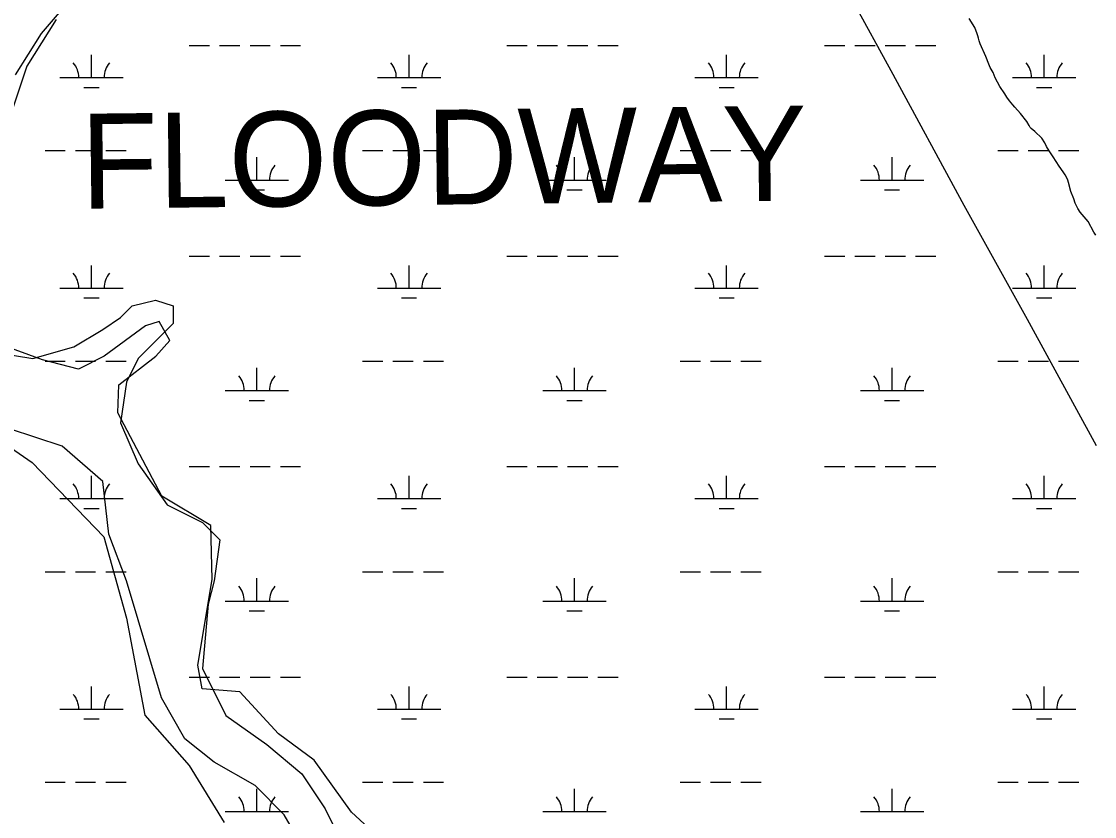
# Model space of a CAD drawing. Extents: x 3177185 to 3215018, y 812988 to 838321.
# Drawn here: x 3187840 to 3189536, y 825317 to 826573 of the extents above; entities that cross this region are included whole.
import ezdxf

# ---------------------------------------------------------------- set-up
doc = ezdxf.new("R2010")
doc.units = 0
for name, color, linetype in [('V-RIVR-IDEN', 7, 'Continuous'), ('V-SITE-VEGE', 7, 'Continuous'), ('V-TOPO-SHOR', 7, 'Continuous'), ('V-WETL-SWMP', 7, 'Continuous')]:
    doc.layers.add(name, color=color, linetype=linetype)

msp = doc.modelspace()

# ---------------------------------------------------------------- linework, layer by layer
at = {"layer": 'V-SITE-VEGE'}
for p, q in [((3187718.2, 825972.5), (3187856.6, 825876.3)), ((3187856.6, 825876.3), (3187969.7, 825759.2)), ((3187969.7, 825759.2), (3188005.9, 825630.4)), ((3188005.9, 825630.4), (3188035, 825477.1)), ((3188035, 825477.1), (3188104.7, 825397.8)), ((3188104.7, 825397.8), (3188160.3, 825307.4))]:
    msp.add_line(p, q, dxfattribs=at)
for points in [[(3189094.5, 826713.4), (3189213.8, 826495.9), (3189328.9, 826283), (3189429.2, 826103), (3189538.3, 825903.2)], [(3187830.5, 826489), (3187871.7, 826554.4), (3187906.1, 826594.7)], [(3189353.4, 826542.7), (3189352.2, 826547.1), (3189351.4, 826550.7), (3189350.2, 826554), (3189346.2, 826563.7), (3189337.7, 826577.9)], [(3189537.8, 826235.6), (3189534.5, 826240.4), (3189525.3, 826257), (3189512.8, 826272), (3189509.1, 826277.7), (3189505.1, 826286.2), (3189502.7, 826293.1), (3189498.2, 826304.4), (3189494.6, 826318.6), (3189493.4, 826322.7), (3189492.2, 826325.1), (3189489, 826331.2), (3189486.2, 826335.6), (3189479.7, 826344.9), (3189470, 826359.5), (3189464, 826368.8), (3189459.9, 826375.7), (3189457.1, 826381.4), (3189452.3, 826388.7), (3189441.4, 826399.6), (3189435.7, 826404.1), (3189434.1, 826405.7), (3189432.1, 826409), (3189428.5, 826415.4), (3189418.8, 826428), (3189409.5, 826438.1), (3189406.6, 826441.4), (3189401.4, 826447.9), (3189397, 826453.9), (3189393.7, 826459.2), (3189385.7, 826470.6), (3189378.8, 826484.3), (3189375.2, 826492.4), (3189370.7, 826500.5), (3189368.3, 826505.8), (3189363.9, 826517.9), (3189355, 826537.8), (3189353.4, 826542.7)], [(3188441.8, 825249.8), (3188361.3, 825323.8), (3188302.2, 825406.1), (3188245.9, 825447.5), (3188184.7, 825514), (3188125.6, 825518.8), (3188118.7, 825556.3), (3188141.2, 825691.3), (3188139.3, 825777.1), (3188061.8, 825823.4), (3187991.9, 825955), (3187993.9, 825999.2), (3188052.1, 826044.3), (3188074.3, 826069.2), (3188057.5, 826099.1), (3188035.9, 826092.4), (3187970.7, 826044.3), (3187929.8, 826023.7), (3187873.1, 826038.6), (3187808.3, 826062.1)]]:
    msp.add_lwpolyline(points, dxfattribs=at)
at = {"layer": 'V-TOPO-SHOR'}
for points in [[(3187894.7, 826576.6), (3187848.5, 826502.7), (3187811.5, 826391.8)], [(3187802.3, 826049.8), (3187857.7, 826040.6), (3187922.4, 826059.1), (3187968.6, 826086.8), (3187996.4, 826105.3), (3188014.8, 826123.8), (3188051.8, 826133), (3188079.5, 826123.8), (3188079.5, 826096), (3188051.8, 826068.3), (3188024.1, 826040.6), (3188005.6, 826003.6), (3187996.4, 825938.9), (3188024.1, 825874.2), (3188070.3, 825809.6), (3188125.7, 825781.8), (3188153.5, 825754.1), (3188144.2, 825689.4), (3188135, 825652.4), (3188125.7, 825550.8), (3188162.7, 825476.9), (3188227.4, 825430.6), (3188282.8, 825384.4), (3188319.8, 825329), (3188356.8, 825255.1)], [(3188319.8, 825208.8), (3188255.1, 825319.7), (3188208.9, 825366), (3188144.2, 825402.9), (3188098, 825439.9), (3188061, 825504.6), (3188005.6, 825689.4), (3187977.9, 825763.3), (3187968.6, 825846.5), (3187903.9, 825902), (3187820.8, 825929.7)]]:
    msp.add_lwpolyline(points, dxfattribs=at)
at = {"layer": 'V-WETL-SWMP'}
for p, q in [((3188105, 826535.4), (3188137, 826535.4)), ((3188153, 826535.4), (3188185, 826535.4)), ((3188201, 826535.4), (3188233, 826535.4)), ((3188249, 826535.4), (3188281, 826535.4)), ((3188606.9, 826535.4), (3188638.9, 826535.4)), ((3188654.9, 826535.4), (3188686.9, 826535.4)), ((3188702.9, 826535.4), (3188734.9, 826535.4)), ((3188750.9, 826535.4), (3188782.9, 826535.4)), ((3189108.8, 826535.4), (3189140.8, 826535.4)), ((3189156.8, 826535.4), (3189188.8, 826535.4)), ((3189204.8, 826535.4), (3189236.8, 826535.4)), ((3189252.8, 826535.4), (3189284.8, 826535.4)), ((3187950.4, 826484.6), (3187950.4, 826520.6)), ((3188452.3, 826484.6), (3188452.3, 826520.6)), ((3188954.2, 826484.6), (3188954.2, 826520.6)), ((3189456.1, 826484.6), (3189456.1, 826520.6)), ((3187900.4, 826484.6), (3188000.4, 826484.6)), ((3188402.3, 826484.6), (3188502.3, 826484.6)), ((3188904.2, 826484.6), (3189004.2, 826484.6)), ((3189406.1, 826484.6), (3189506.1, 826484.6)), ((3187938.4, 826469.2), (3187962.4, 826469.2)), ((3188440.3, 826469.2), (3188464.3, 826469.2)), ((3188942.2, 826469.2), (3188966.2, 826469.2)), ((3189444.1, 826469.2), (3189468.1, 826469.2)), ((3187877, 826369.2), (3187909, 826369.2)), ((3187925, 826369.2), (3187957, 826369.2)), ((3187973, 826369.2), (3188005, 826369.2)), ((3188211.8, 826322.7), (3188211.8, 826358.7)), ((3188378.9, 826369.2), (3188410.9, 826369.2)), ((3188426.9, 826369.2), (3188458.9, 826369.2)), ((3188474.9, 826369.2), (3188506.9, 826369.2)), ((3188713.7, 826322.7), (3188713.7, 826358.7)), ((3188880.8, 826369.2), (3188912.8, 826369.2)), ((3188928.8, 826369.2), (3188960.8, 826369.2)), ((3188976.8, 826369.2), (3189008.8, 826369.2)), ((3189215.6, 826322.7), (3189215.6, 826358.7)), ((3189382.7, 826369.2), (3189414.7, 826369.2)), ((3189430.7, 826369.2), (3189462.7, 826369.2)), ((3189478.7, 826369.2), (3189510.7, 826369.2)), ((3188161.8, 826322.7), (3188261.8, 826322.7)), ((3188199.8, 826307.3), (3188223.8, 826307.3)), ((3188663.7, 826322.7), (3188763.7, 826322.7)), ((3188701.7, 826307.3), (3188725.7, 826307.3)), ((3189165.6, 826322.7), (3189265.6, 826322.7)), ((3189203.6, 826307.3), (3189227.6, 826307.3)), ((3187950.4, 826151.9), (3187950.4, 826187.9)), ((3188105, 826202.7), (3188137, 826202.7)), ((3188153, 826202.7), (3188185, 826202.7)), ((3188201, 826202.7), (3188233, 826202.7)), ((3188249, 826202.7), (3188281, 826202.7)), ((3188452.3, 826151.9), (3188452.3, 826187.9)), ((3188606.9, 826202.7), (3188638.9, 826202.7)), ((3188654.9, 826202.7), (3188686.9, 826202.7)), ((3188702.9, 826202.7), (3188734.9, 826202.7)), ((3188750.9, 826202.7), (3188782.9, 826202.7)), ((3188954.2, 826151.9), (3188954.2, 826187.9)), ((3189108.8, 826202.7), (3189140.8, 826202.7)), ((3189156.8, 826202.7), (3189188.8, 826202.7)), ((3189204.8, 826202.7), (3189236.8, 826202.7)), ((3189252.8, 826202.7), (3189284.8, 826202.7)), ((3189456.1, 826151.9), (3189456.1, 826187.9)), ((3187900.4, 826151.9), (3188000.4, 826151.9)), ((3188402.3, 826151.9), (3188502.3, 826151.9)), ((3188904.2, 826151.9), (3189004.2, 826151.9)), ((3189406.1, 826151.9), (3189506.1, 826151.9)), ((3187938.4, 826136.5), (3187962.4, 826136.5)), ((3188440.3, 826136.5), (3188464.3, 826136.5)), ((3188942.2, 826136.5), (3188966.2, 826136.5)), ((3189444.1, 826136.5), (3189468.1, 826136.5)), ((3187877, 826036.5), (3187909, 826036.5)), ((3187925, 826036.5), (3187957, 826036.5)), ((3187973, 826036.5), (3188005, 826036.5)), ((3188378.9, 826036.5), (3188410.9, 826036.5)), ((3188426.9, 826036.5), (3188458.9, 826036.5)), ((3188474.9, 826036.5), (3188506.9, 826036.5)), ((3188880.8, 826036.5), (3188912.8, 826036.5)), ((3188928.8, 826036.5), (3188960.8, 826036.5)), ((3188976.8, 826036.5), (3189008.8, 826036.5)), ((3189382.7, 826036.5), (3189414.7, 826036.5)), ((3189430.7, 826036.5), (3189462.7, 826036.5)), ((3189478.7, 826036.5), (3189510.7, 826036.5)), ((3188211.8, 825990.1), (3188211.8, 826026.1)), ((3188713.7, 825990.1), (3188713.7, 826026.1)), ((3189215.6, 825990.1), (3189215.6, 826026.1)), ((3188161.8, 825990.1), (3188261.8, 825990.1)), ((3188663.7, 825990.1), (3188763.7, 825990.1)), ((3189165.6, 825990.1), (3189265.6, 825990.1)), ((3188199.8, 825974.6), (3188223.8, 825974.6)), ((3188701.7, 825974.6), (3188725.7, 825974.6)), ((3189203.6, 825974.6), (3189227.6, 825974.6)), ((3188105, 825870), (3188137, 825870)), ((3188153, 825870), (3188185, 825870)), ((3188201, 825870), (3188233, 825870)), ((3188249, 825870), (3188281, 825870)), ((3188606.9, 825870), (3188638.9, 825870)), ((3188654.9, 825870), (3188686.9, 825870)), ((3188702.9, 825870), (3188734.9, 825870)), ((3188750.9, 825870), (3188782.9, 825870)), ((3189108.8, 825870), (3189140.8, 825870)), ((3189156.8, 825870), (3189188.8, 825870)), ((3189204.8, 825870), (3189236.8, 825870)), ((3189252.8, 825870), (3189284.8, 825870)), ((3187950.4, 825819.3), (3187950.4, 825855.3)), ((3188452.3, 825819.3), (3188452.3, 825855.3)), ((3188954.2, 825819.3), (3188954.2, 825855.3)), ((3189456.1, 825819.3), (3189456.1, 825855.3)), ((3187900.4, 825819.3), (3188000.4, 825819.3)), ((3188402.3, 825819.3), (3188502.3, 825819.3)), ((3188904.2, 825819.3), (3189004.2, 825819.3)), ((3189406.1, 825819.3), (3189506.1, 825819.3)), ((3187938.4, 825803.8), (3187962.4, 825803.8)), ((3188440.3, 825803.8), (3188464.3, 825803.8)), ((3188942.2, 825803.8), (3188966.2, 825803.8)), ((3189444.1, 825803.8), (3189468.1, 825803.8)), ((3187877, 825703.8), (3187909, 825703.8)), ((3187925, 825703.8), (3187957, 825703.8)), ((3187973, 825703.8), (3188005, 825703.8)), ((3188378.9, 825703.8), (3188410.9, 825703.8)), ((3188426.9, 825703.8), (3188458.9, 825703.8)), ((3188474.9, 825703.8), (3188506.9, 825703.8)), ((3188880.8, 825703.8), (3188912.8, 825703.8)), ((3188928.8, 825703.8), (3188960.8, 825703.8)), ((3188976.8, 825703.8), (3189008.8, 825703.8)), ((3189382.7, 825703.8), (3189414.7, 825703.8)), ((3189430.7, 825703.8), (3189462.7, 825703.8)), ((3189478.7, 825703.8), (3189510.7, 825703.8)), ((3188211.8, 825657.4), (3188211.8, 825693.4)), ((3188713.7, 825657.4), (3188713.7, 825693.4)), ((3189215.6, 825657.4), (3189215.6, 825693.4)), ((3188161.8, 825657.4), (3188261.8, 825657.4)), ((3188663.7, 825657.4), (3188763.7, 825657.4)), ((3189165.6, 825657.4), (3189265.6, 825657.4)), ((3188199.8, 825642), (3188223.8, 825642)), ((3188701.7, 825642), (3188725.7, 825642)), ((3189203.6, 825642), (3189227.6, 825642)), ((3188105, 825537.3), (3188137, 825537.3)), ((3188153, 825537.3), (3188185, 825537.3)), ((3188201, 825537.3), (3188233, 825537.3)), ((3188249, 825537.3), (3188281, 825537.3)), ((3188606.9, 825537.3), (3188638.9, 825537.3)), ((3188654.9, 825537.3), (3188686.9, 825537.3)), ((3188702.9, 825537.3), (3188734.9, 825537.3)), ((3188750.9, 825537.3), (3188782.9, 825537.3)), ((3189108.8, 825537.3), (3189140.8, 825537.3)), ((3189156.8, 825537.3), (3189188.8, 825537.3)), ((3189204.8, 825537.3), (3189236.8, 825537.3)), ((3189252.8, 825537.3), (3189284.8, 825537.3)), ((3187950.4, 825486.6), (3187950.4, 825522.6)), ((3188452.3, 825486.6), (3188452.3, 825522.6)), ((3188954.2, 825486.6), (3188954.2, 825522.6)), ((3189456.1, 825486.6), (3189456.1, 825522.6)), ((3187900.4, 825486.6), (3188000.4, 825486.6)), ((3188402.3, 825486.6), (3188502.3, 825486.6)), ((3188904.2, 825486.6), (3189004.2, 825486.6)), ((3189406.1, 825486.6), (3189506.1, 825486.6)), ((3187938.4, 825471.2), (3187962.4, 825471.2)), ((3188440.3, 825471.2), (3188464.3, 825471.2)), ((3188942.2, 825471.2), (3188966.2, 825471.2)), ((3189444.1, 825471.2), (3189468.1, 825471.2)), ((3187877, 825371.2), (3187909, 825371.2)), ((3187925, 825371.2), (3187957, 825371.2)), ((3187973, 825371.2), (3188005, 825371.2)), ((3188211.8, 825324.7), (3188211.8, 825360.7)), ((3188378.9, 825371.2), (3188410.9, 825371.2)), ((3188426.9, 825371.2), (3188458.9, 825371.2)), ((3188474.9, 825371.2), (3188506.9, 825371.2)), ((3188713.7, 825324.7), (3188713.7, 825360.7)), ((3188880.8, 825371.2), (3188912.8, 825371.2)), ((3188928.8, 825371.2), (3188960.8, 825371.2)), ((3188976.8, 825371.2), (3189008.8, 825371.2)), ((3189215.6, 825324.7), (3189215.6, 825360.7)), ((3189382.7, 825371.2), (3189414.7, 825371.2)), ((3189430.7, 825371.2), (3189462.7, 825371.2)), ((3189478.7, 825371.2), (3189510.7, 825371.2)), ((3188161.8, 825324.7), (3188261.8, 825324.7)), ((3188663.7, 825324.7), (3188763.7, 825324.7)), ((3189165.6, 825324.7), (3189265.6, 825324.7))]:
    msp.add_line(p, q, dxfattribs=at)
for centre, start, end in [((3187895.1, 826485.1), 359.2282, 40.7718), ((3188005.6, 826485.1), 139.2282, 180.7718), ((3188397, 826485.1), 359.2282, 40.7718), ((3188507.5, 826485.1), 139.2282, 180.7718), ((3188898.9, 826485.1), 359.2282, 40.7718), ((3189009.4, 826485.1), 139.2282, 180.7718), ((3189400.8, 826485.1), 359.2282, 40.7718), ((3189511.3, 826485.1), 139.2282, 180.7718), ((3188156.6, 826323.2), 359.2282, 40.7718), ((3188267, 826323.2), 139.2282, 180.7718), ((3188658.5, 826323.2), 359.2282, 40.7718), ((3188768.9, 826323.2), 139.2282, 180.7718), ((3189160.4, 826323.2), 359.2282, 40.7718), ((3189270.9, 826323.2), 139.2282, 180.7718), ((3187895.1, 826152.4), 359.2282, 40.7718), ((3188005.6, 826152.4), 139.2282, 180.7718), ((3188397, 826152.4), 359.2282, 40.7718), ((3188507.5, 826152.4), 139.2282, 180.7718), ((3188898.9, 826152.4), 359.2282, 40.7718), ((3189009.4, 826152.4), 139.2282, 180.7718), ((3189400.8, 826152.4), 359.2282, 40.7718), ((3189511.3, 826152.4), 139.2282, 180.7718), ((3188156.6, 825990.5), 359.2282, 40.7718), ((3188267, 825990.5), 139.2282, 180.7718), ((3188658.5, 825990.5), 359.2282, 40.7718), ((3188768.9, 825990.5), 139.2282, 180.7718), ((3189160.4, 825990.5), 359.2282, 40.7718), ((3189270.9, 825990.5), 139.2282, 180.7718), ((3187895.1, 825819.7), 359.2282, 40.7718), ((3188005.6, 825819.7), 139.2282, 180.7718), ((3188397, 825819.7), 359.2282, 40.7718), ((3188507.5, 825819.7), 139.2282, 180.7718), ((3188898.9, 825819.7), 359.2282, 40.7718), ((3189009.4, 825819.7), 139.2282, 180.7718), ((3189400.8, 825819.7), 359.2282, 40.7718), ((3189511.3, 825819.7), 139.2282, 180.7718), ((3188156.6, 825657.9), 359.2282, 40.7718), ((3188267, 825657.9), 139.2282, 180.7718), ((3188658.5, 825657.9), 359.2282, 40.7718), ((3188768.9, 825657.9), 139.2282, 180.7718), ((3189160.4, 825657.9), 359.2282, 40.7718), ((3189270.9, 825657.9), 139.2282, 180.7718), ((3187895.1, 825487.1), 359.2282, 40.7718), ((3188005.6, 825487.1), 139.2282, 180.7718), ((3188397, 825487.1), 359.2282, 40.7718), ((3188507.5, 825487.1), 139.2282, 180.7718), ((3188898.9, 825487.1), 359.2282, 40.7718), ((3189009.4, 825487.1), 139.2282, 180.7718), ((3189400.8, 825487.1), 359.2282, 40.7718), ((3189511.3, 825487.1), 139.2282, 180.7718), ((3188156.6, 825325.2), 359.2282, 40.7718), ((3188267, 825325.2), 139.2282, 180.7718), ((3188658.5, 825325.2), 359.2282, 40.7718), ((3188768.9, 825325.2), 139.2282, 180.7718), ((3189160.4, 825325.2), 359.2282, 40.7718), ((3189270.9, 825325.2), 139.2282, 180.7718)]:
    msp.add_arc(centre, 35.2, start, end, dxfattribs=at)

# ---------------------------------------------------------------- texts
at = {"layer": 'V-RIVR-IDEN'}
msp.add_text('FLOODWAY', height=150, rotation=0.6511, dxfattribs=at).set_placement((3187933.9, 826277.4))

doc.saveas('drawing.dxf')
